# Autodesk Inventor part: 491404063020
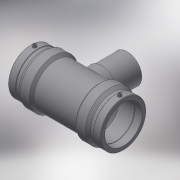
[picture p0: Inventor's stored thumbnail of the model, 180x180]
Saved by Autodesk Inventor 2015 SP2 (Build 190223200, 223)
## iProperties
Created: 2017-06
Part Number: 491404063020
Material: Generic
Description: PLASSON REDUCING TEE 63x20x63
Document SubType Name: Modeling
Designer: KIM
Mass: 355.763 g
Surface Area: 864.814 cm^2
Volume: 355.763 cm^3
Density: 1 g/cm^3
Appearance: Default
Author: KIM
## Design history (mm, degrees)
derived "491404.ipt"
feature "Solid1::491404.ipt"
tag "TaggingFeature1"
body "Solid1"
other parameters: "d0" = 167, "d1" = 63, "d2" = 82, "d3" = 49, "d4" = 33.4, "d5" = 73.8, "d6" = 59.85, "d7" = 63, "d8" = 168 deg, "d10" = 19.6, "d11" = 6.53333, "d13" = 167, "d14" = 17.6296, "d17" = 56.7, "d18" = 63, "d19" = 3.52592, "d20" = 168 deg, "d22" = 76.26, "d23" = 82, "d25" = 135 deg, "d26" = 116.9, "d29" = 58, "d30" = 15, "d31" = 66.8, "d34" = 5 deg, "d35" = 15, "d39" = 5 deg, "d41" = 4, "d42" = 14, "d43" = 0, "d45" = 4, "d46" = 6, "d47" = 0, "d48" = -85, "d51" = 0, "d52" = 16, "d54" = 0, "d55" = 73.8, "d56" = 82, "d57" = 58.45, "d58" = 135 deg, "d59" = 49, "d60" = 49, "d61" = 135 deg, "d62" = 85, "d72" = 75.985, "d73" = 37.9925, "d74" = -85, "d75" = 21, "d77" = 0, "d78" = 16, "d80" = 0, "d82" = 44, "d83" = 0, "d84" = 3, "d85" = 0, "d86" = 16.33333, "d87" = 74.7348, "d88" = 6.53333, "d89" = 3, "d90" = 0, "d_" = 63, "L_" = 167, "L_1" = 49, "D_" = 82, "A_" = 58, "d_2" = 12, "H_" = 85
